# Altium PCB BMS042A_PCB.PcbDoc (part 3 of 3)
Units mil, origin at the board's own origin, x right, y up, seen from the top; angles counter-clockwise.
Board outline 4409.45 x 3307 mil, 6 copper layers (Top Layer, Layer 2 - PGND, Layer 3, Layer 4, Layer 5 - PGND, Bottom Layer), stack 60.8 mil thick; 273 components, 77 nets, 544 pads, 927 vias.
Unrouted connection lines stored in the file: 219.
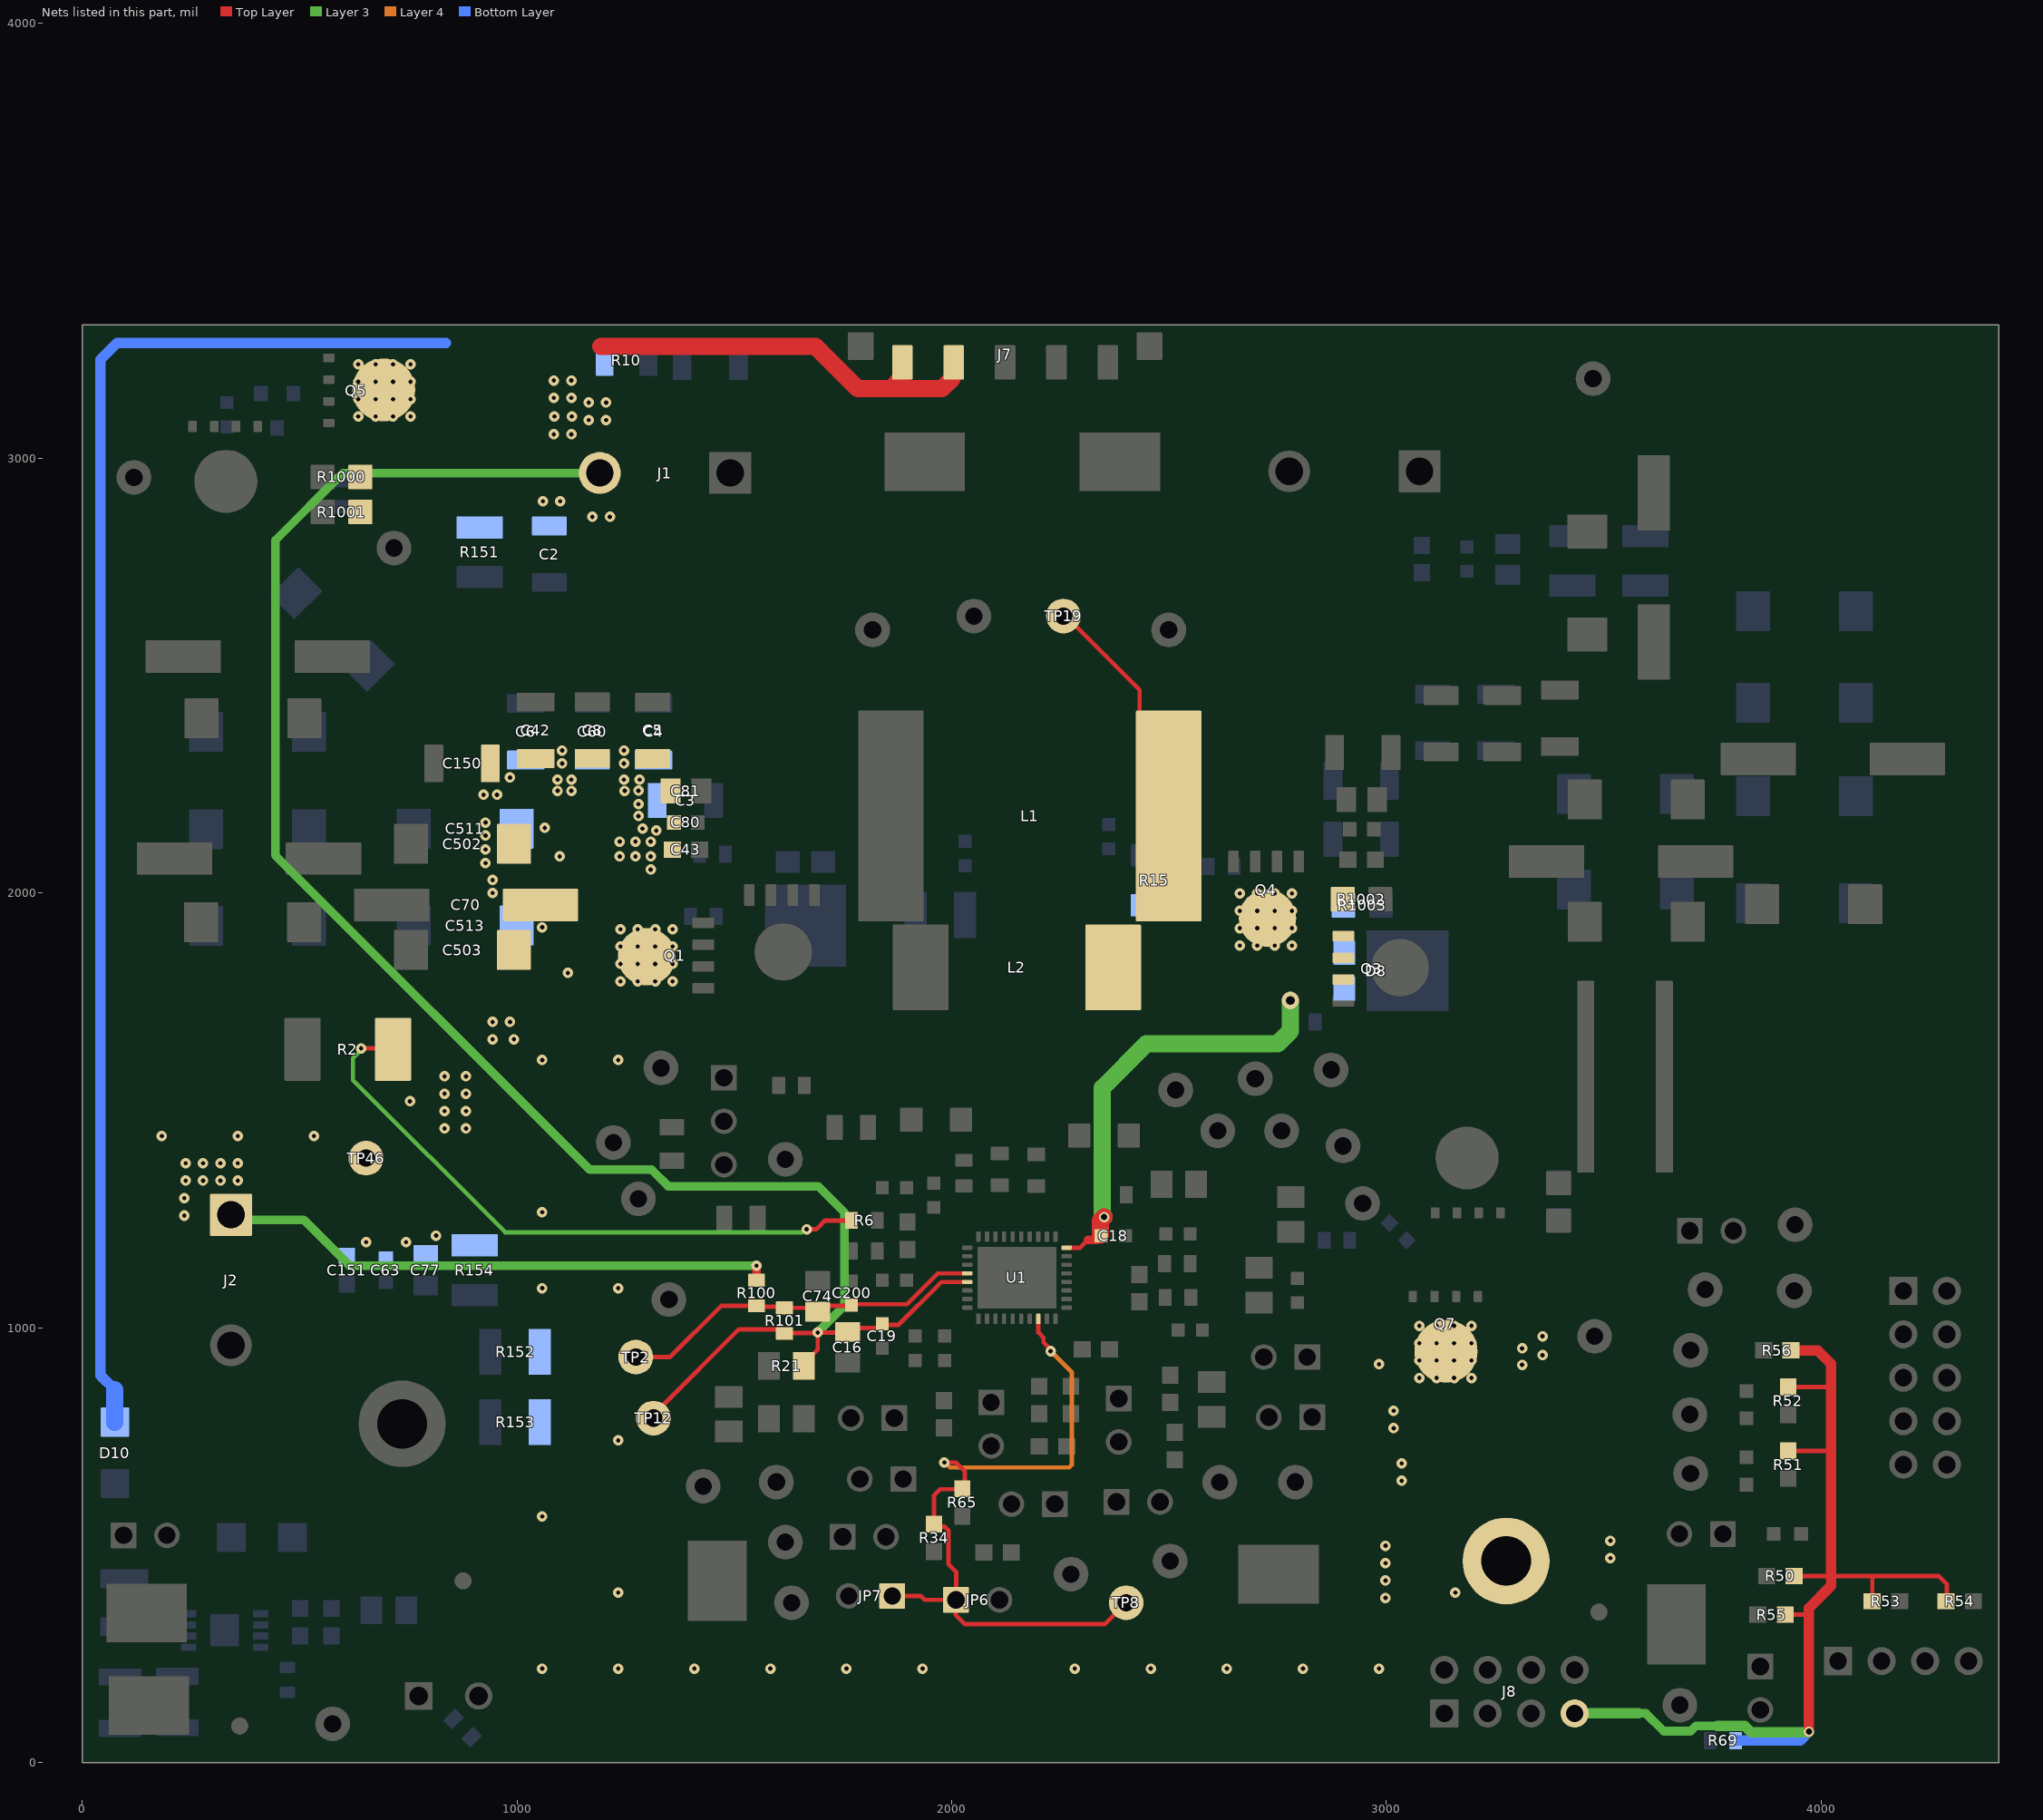
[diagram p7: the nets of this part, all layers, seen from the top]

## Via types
v1: diameter 24, hole 10, Top Layer to Bottom Layer, tented both sides, 653 vias
v2: diameter 24, hole 9.8, Top Layer to Bottom Layer, tented both sides, 132 vias
v3: diameter 24, hole 14, Top Layer to Bottom Layer, tented both sides, 105 vias
v4: diameter 40, hole 20, Top Layer to Bottom Layer, tented both sides, 21 vias
v5: diameter 19.68, hole 7.87, Top Layer to Bottom Layer, tented both sides, 16 vias

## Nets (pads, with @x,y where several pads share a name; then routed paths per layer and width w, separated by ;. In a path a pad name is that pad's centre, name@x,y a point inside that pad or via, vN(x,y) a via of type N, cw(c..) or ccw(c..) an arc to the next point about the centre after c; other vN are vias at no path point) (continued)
SW2: C18.2 D8.1 D8.2 L1.2 L2.2 Q3.1 Q3.2 Q3.3 Q4.5-6-7-8 R15.2 R1002.1 R1003.1 TP19.1 U1.18 | length 1557.2
  Top Layer w9.84: U1.18@2264.2,1184.14 2295.58,1184.14 2307.09,1195.65
  Top Layer w10: TP19.1@2257.14,2637 2262.19,2637 2432.23,2466.96 2432.23,2243.89 L1.2@2499.14,2176.98 ; 2307.09,1195.65 2313.22,1201.78 ; C18.2@2333.89,1201.78 C18.2@2343.89,1211.78 C18.2@2342.36,1213.31
  Top Layer w20: 2313.22,1201.78 C18.2@2333.89,1201.78
  Top Layer w40: C18.2@2342.36,1213.31 2342.36,1246.63 v3(2350.49,1254.76)
  Layer 3 w40: v3(2350.49,1254.76) 2346.55,1258.71 2346.55,1551.7 2448.01,1653.16 2750,1653.16 2779.2,1682.35 2779.2,1747.25 2779.02,1747.43 v4(2779.02,1752.79)
  other v2: 2662.9,1879.01 2702.9,1879.01 2742.9,1879.01 2782.9,1879.01 2662.9,1919.01 2702.9,1919.01 2742.9,1919.01 2782.9,1919.01 2662.9,1959.01 2702.9,1959.01 2742.9,1959.01 2782.9,1959.01 2662.9,1999.01 2702.9,1999.01 2742.9,1999.01 2782.9,1999.01
SYS: C74.1 C200.1 R100.1 R101.2 TP2.1 U1.32 | length 848.7
  Top Layer w9.84: 1967.91,1125.09 U1.32@2035.85,1125.09
  Top Layer w10: TP2.1@1273.45,932.59 1351.94,932.59 1469.74,1050.39 R100.1@1551.11,1050.39 1553.42,1048.08 R101.2@1612.97,1048.08 ; R101.2@1615.29,1045.77 1682.9,1045.77 C74.1@1691.61,1037.06 ; C74.1@1690.6,1050.28 1768.18,1050.28 C200.1@1769.58,1051.68 1772.12,1054.22 1897.12,1054.22 1967.91,1125.01
  Top Layer w20: R101.2@1612.97,1048.08 R101.2@1615.29,1045.77
TS: JP6.1 JP7.1 R34.1 R65.2 TP8.1 U1.8 | length 1718.5
  Top Layer w9.84: 2199.23,989.1 U1.8@2199.23,1020.76
  Top Layer w10: JP7.1@1863.1,383.15 1928.48,383.15 1937.56,374.06 JP6.1@2009.85,374.06 ; v1(1983.09,690) 2010.14,690 2030.1,670.04 2030.1,635.59 2024.4,629.89 R65.2@2024.57,629.73 2023.38,628.54 1973.23,628.54 1959.43,614.74 R34.1@1959.43,548.32 1959.43,547.33 1964.28,542.49 1984.17,542.49 1992.97,533.69 1992.97,455.32 2010.62,437.68 2010.62,374.83 JP6.1@2009.85,374.06 ; 2199.31,989.13 2211.07,977.37 2211.07,966.31 2227.42,949.96 v1(2227.42,946.17) ; TP8.1@2401.38,367.5 2351.96,318.08 2030.53,318.08 2009.27,339.34 2009.27,373.48 JP6.1@2009.85,374.06
  Layer 4 w10: v1(1983.09,690) 1984.75,690 1995.95,678.8 2270.51,678.8 2276.36,684.66 2276.36,897.23 v1(2227.42,946.17)
VAC: C2.2 C16.1 C19.1 D10.2 J1.2 J7.4 J7.5 Q5.5-6-7-8 R10.2 R21.2 R101.1 R151.2 R1000.1 R1001.1 TP12.1 U1.33 | length 8694.4
  Top Layer w9.84: 1970.39,1099.43 1970.39,1099.54 1976.25,1105.4 U1.33@2035.85,1105.4
  Top Layer w10: TP12.1@1314.24,760.32 TP12.1@1314.24,808.29 ; TP12.1@1331,816.81 1510.48,996.29 1605.71,996.29 R101.1@1615.29,986.72 1616.48,987.91 1690.42,987.91 v1(1691.61,989.1) ; R21.2@1659.96,912.07 1659.96,918.57 1691.61,950.22 v1(1691.61,989.1) ; C19.1@1840.37,1006.65 1877.61,1006.65 1970.39,1099.43 ; C19.1@1840.37,1009.03 1830.81,999.46 1769.89,999.46 C16.1@1760.89,990.46 1759.53,989.1 v1(1691.61,989.1)
  Top Layer w40: 1192.48,3257 1686.95,3257 1783.96,3160 1859.64,3160 ; J7.5@1886.69,3220.53 1883.07,3216.91 1883.07,3183.43 1859.64,3160 ; J7.4@2004.8,3220.53 2001.18,3216.91 2001.18,3183.43 1977.75,3160 1859.64,3160
  Layer 3 w20: J1.2@1190.42,2966.06 599.06,2966.06 444.49,2811.49 444.49,2086.51 1167.49,1363.51 1310.1,1363.51 1347.99,1325.63 1692.8,1325.63 1753.69,1264.73 1753.69,1051.18 v1(1691.61,989.1)
  Bottom Layer w24: 75,857.5 42,890.5 42,3226.94 80.06,3265 836.73,3265
  Bottom Layer w40: D10.2@75,782.97 75,857.5
  other v1: 1173.64,2865.32 1213.64,2865.32 1059.62,2901.32 1099.62,2901.32 1085,3055 1125,3055 1165,3088 1205,3088 1086.2,3095.93 1126.2,3095.93 1165,3128 1205,3128 1085,3139 1125,3139 1085,3179 1125,3179
  other v2: 635,3096 675,3096 715,3096 755,3096 635,3136 675,3136 715,3136 755,3136 635,3176 675,3176 715,3176 755,3176 635,3216 675,3216 715,3216 755,3216
VIN3V3: J8.7 R50.2 R51.2 R52.2 R53.2 R54.2 R55.2 R56.2 R69.2 | length 2429.6
  Top Layer w10: R55.2@3917.5,340 3972,340 ; R52.2@3924,863.5 4018.24,863.5 4022.98,858.76 ; R51.2@3924.56,716.6 4020.57,716.6 4022.98,719 ; R50.2@3937.54,429 4022.98,429 4119,429 ; R53.2@4117.5,371 4117.5,427.5 4119,429 ; R54.2@4290.5,371 4289,372.5 4289,410.16 4270.16,429 4119,429
  Top Layer w24: R56.2@3930.5,948 3992,948 4022.98,917.02 4022.98,858.76 4022.98,719 4022.98,429 4022.98,406.28 3972,355.3 3972,340 v3(3972,71)
  Layer 3 w20: 3579.97,113 3597,113 3637.84,72.16 3699.79,72.16 3711.92,84.29 3760.83,84.29
  Layer 3 w24: J8.7@3433,113 3579.97,113 ; 3760.83,84.29 3824.06,84.29 3838.72,69.63 3970.63,69.63 v3(3972,71)
  Bottom Layer w24: R69.2@3803.53,50.37 3804.16,51 3952,51 v3(3972,71)
VSYS: C3.1 C4.1 C5.2 C6.1 C8.2 C42.2 C43.1 C60.1 C63.1 C70.2 C77.1 C80.1 C81.1 C150.2 C151.1 C502.2 C503.2 C511.2 C513.2 J2.1 pad.Pad1 Q1.5-6-7-8 Q7.5-6-7-8 R2.2 R6.2 R100.2 R152.2 R153.2 R154.2 TP46.1 | length 2748.3
  Top Layer w10: v1(641.66,1642.82) 712.64,1642.82 R2.2@714.95,1640.5 ; v1(1666.43,1226.63) 1688.77,1226.63 1708.69,1246.56 R6.2@1769.13,1246.56
  Top Layer w20: R100.2@1551.11,1109.45 v1(1551.11,1142.91)
  Layer 3 w10: v1(641.66,1642.82) 641.66,1639.03 623,1620.37 623,1569.5 972.87,1219.63 1655.64,1219.63 1662.64,1226.63 v1(1666.43,1226.63)
  Layer 3 w20: J2.1@342.13,1259.78 353.66,1248.25 509.25,1248.25 614.59,1142.91 v1(1551.11,1142.91)
  other v1: 1058,216 1233,216 1408,216 1583,216 1758,216 1933,216 2283,216 2458,216 2633,216 2808,216 2983,216 2998.01,378.52 1233,391 3158.45,390.71 2998.01,418.52 2998.01,458.52 3515.1,470.12 2998.01,498.52 3515.1,510.12 1058,566 3035.1,647.91 3035.1,687.91 1233,741 3016.59,769.13 3016.59,809.13 3312,914.85 2983,916 3359,936.87 3312,952.64 3359,980.4 1058,1091 1233,1091 653,1197 745,1197 814,1212 235,1258 1058,1266 235,1298 238,1338.61 278,1338.61 318,1338.61 358,1338.61 238,1378.61 278,1378.61 318,1378.61 358,1378.61 183,1441 358,1441 533,1441 833.55,1458.45 882.81,1458.45 833.55,1498.45 882.81,1498.45 754,1521 833.55,1538.45 882.81,1538.45 833.55,1578.45 882.81,1578.45 1058,1616 1233,1616 943.9,1663.4 993.16,1663.4 943.9,1703.4 983.95,1703.4 1117,1816 1058.04,1921.2 943.95,1999.99 943.9,2030 1307.79,2054 927.58,2069.01 1098.49,2084 1236.46,2084 1272.48,2084 1307.79,2084 927.58,2100 1236.46,2118.27 1272.48,2118.27 1307.79,2118.27 927.58,2132 1320.71,2143.66 1288.74,2148.22 1063.95,2149.84 927.58,2162.04 1279.4,2176.98 1279.4,2204.55 923,2225.92 954,2225.92 1093.62,2235.16 1125,2235 1247.74,2235 1279.39,2235.23 1093.62,2260.73 1125,2260.73 1246,2260.73 1282.16,2260.73 983.95,2265.72 1103.95,2297.91 1246,2297.91 1104,2328 1246,2328
  other v2: 3075.65,884.56 3115.65,884.56 3155.65,884.56 3195.65,884.56 3075.65,924.56 3115.65,924.56 3155.65,924.56 3195.65,924.56 3075.65,964.56 3115.65,964.56 3155.65,964.56 3195.65,964.56 3075.65,1004.56 3115.65,1004.56 3155.65,1004.56 3195.65,1004.56 1237.97,1796.89 1277.97,1796.89 1317.97,1796.89 1357.97,1796.89 1237.97,1836.89 1277.97,1836.89 1317.97,1836.89 1357.97,1836.89 1237.97,1876.89 1277.97,1876.89 1317.97,1876.89 1357.97,1876.89 1237.97,1916.89 1277.97,1916.89 1317.97,1916.89 1357.97,1916.89
pads on no net: D1.2 FID1.1 FID2.1 FID3.1 FID4.1 FID5.1 FID6.1 H1.0 H2.0 H3.0 H4.0 J4.1 J4.2 J4.3 J4.4 J4.5 J4.7 J4.8 J5.4 LBL1.0 SH-JP1.0 SH-JP2.0 SH-JP3.0 SH-JP4.0 SH-JP5.0 SH-JP6.0 SH-JP7.0 SH-JP8.0 SH-JP9.0 SH-JP10.0 SH-JP11.0 U2.3 U2.6 U2.7

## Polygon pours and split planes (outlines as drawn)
PGND on Top Layer "TOP_LAYER_PGND_P669" (solid, remove dead copper, pour order 669): 1,3310 1,-1 4409.45,-1 4409.45,3304.45 4410,3305 2,3305 0,3307
BAT on Top Layer "TOP_LAYER_BAT_P668" (solid, remove dead copper, pour order 668): 3428,1838.67 3428,1307 4434,1307 4434,3309 4436,3311 2939.16,3311 2939.16,2781 3971,2781 3971,1838.67
VSYS on Top Layer "Top Layer-NetC3_1" (solid, remove dead copper, pour order 621): 0,1145 1001,1145 1001,-1 3539.82,-1 3539.82,1052.11 2944.31,1052.11 2944.31,318.08 1326.85,318.08 1326.85,1443.5 1376.14,1443.5 1376.14,2350.2 897.88,2350.2 897.88,1792.06 623,1791.94 623,1479.85 0,1480.09
SW1 on Top Layer "TOP_LAYER_SW1_P636" (solid, remove dead copper, pour order 636): 1387.59,1942.21 1759.9,1942.21 1759.9,2443.4 1999.6,2443.4 2035.85,2443.4 2035.85,1640.5 1387.59,1640.5
AC_OUT on Top Layer "Top Layer-NetC7_2" (solid, remove dead copper, pour order 626): -26,1468 679.82,1468 679.82,1794 429,1794 429,2615.1 584,2615.1 584,3032 -25,3032 -25,2980 -26,2979
NetC9_1 on Top Layer "TOP_LAYER_NETC9_1_P627" (solid, remove dead copper, pour order 627): 585,3312 583,3310 583,3055 -14,3055 -14,3314 584,3314
P_OUT on Top Layer "TOP_LAYER_P_OUT_P628" (solid, remove dead copper, pour order 628): 2955.65,1305.62 3539.82,1305.62 3539.82,2372.28 2955.65,2372.28
BAT_SRC on Top Layer "TOP_LAYER_BAT_SRC_P607" (solid, remove dead copper, pour order 607): 2955.65,1280.39 3539.82,1280.39 3539.82,1054.04 2955.65,1054.04
VAC on Top Layer "TOP_LAYER_VAC_P616" (solid, remove dead copper, pour order 616): 1328.47,3314 1328.47,2795.71 610,2795.71 610,2918.6 610,3314
SW2 on Top Layer "TOP_LAYER_SW2_P662" (solid, remove dead copper, pour order 662): 2254.33,2443.4 2254.33,1720.27 2932.21,1720.27 2933.1,1721.16 2929,1725.26 2929,2019.87 2591.58,2019.87 2591.58,2443.4
PGND on Layer 3 "LAYER_3_-_PGND_PGND_P550" (solid, remove dead copper, pour order 673): 4409.45,-5 5,-5 0,0 0,3343.16 4409.45,3343.16
VAC on Layer 3 "Layer 3-VAC" (solid, remove dead copper, pour order 603): 460,2881.6 1282.14,2881.6 1280,2883.74 1280,3311 0,3311 0,3119.74 460,3119.74
AC_OUT on Layer 3 "LAYER_3_AC_OUT_P657" (solid, remove dead copper, pour order 657): 0,3134 444.49,3134 444.49,2343.58 0,2343.58
P_OUT on Layer 3 "LAYER_3_P_OUT_P658" (solid, remove dead copper, pour order 658): 2674.99,2096.96 2674.99,1598.6 3359.4,1598.6 3465,1598.6 3465,2096.96
P_OUT on Layer 3 "LAYER_3_P_OUT_P659" (solid, remove dead copper, pour order 659): 3011.93,1152.03 3405.1,1152.03 3405.1,1662.47 3011.93,1662.47
VSYS on Layer 3 "LAYER_3_VSYS_P660" (solid, remove dead copper, pour order 660): 1081.81,2139.21 1085,2136.02 1085,1676 1495.82,1676 1486.12,1685.69 1486.12,2139.21
VSYS on Layer 3 "LAYER_3_VSYS_P672" (solid, remove dead copper, pour order 672): 2925.9,839.53 3481.13,839.53 3481.13,1088 2925.9,1088
PGND on Layer 4 "LAYER_4_PGND_P671" (solid, remove dead copper, pour order 671): 1,3310 1,-1 4409.45,-1 4409.45,3304.45 4410,3305 2,3305 0,3307
BAT on Layer 4 "LAYER_4_BAT_P670" (solid, remove dead copper, pour order 670): 3428,1838.67 3428,1307 4434,1307 4434,3309 4436,3311 2939.16,3311 2939.16,2781 3971,2781 3971,1838.67
VSYS on Layer 4 "LAYER_4_VSYS_P640" (solid, remove dead copper, pour order 640): 0,1145 1001,1145 1001,-1 3539.82,-1 3539.82,1052.11 2944.31,1052.11 2944.31,318.08 1326.85,318.08 1326.85,1443.5 1376.14,1443.5 1376.14,2350.2 897.88,2350.2 897.88,1792.06 623,1791.94 623,1479.85 0,1480.09
AC_OUT on Layer 4 "LAYER_4_AC_OUT_P641" (solid, remove dead copper, pour order 641): -26,1468 679.82,1468 679.82,1794 429,1794 429,2615.1 584,2615.1 584,3032 -25,3032 -25,2980 -26,2979
P_OUT on Layer 4 "LAYER_4_P_OUT_P643" (solid, remove dead copper, pour order 643): 2955.65,1305.62 3539.82,1305.62 3539.82,2372.28 2955.65,2372.28
BAT_SRC on Layer 4 "LAYER_4_BAT_SRC_P637" (solid, remove dead copper, pour order 637): 2955.65,1280.39 3539.82,1280.39 3539.82,1054.04 2955.65,1054.04
VAC on Layer 4 "LAYER_4_VAC_P639" (solid, remove dead copper, pour order 639): 1328.47,3314 1328.47,2795.71 610,2795.71 610,2918.6 610,3314
NetC9_1 on Layer 4 "LAYER_4_NETC9_1_P642" (solid, remove dead copper, pour order 642): 585,3312 583,3310 583,3055 -14,3055 -14,3314 584,3314
SW1 on Layer 4 "LAYER_4_SW1_P644" (solid, remove dead copper, pour order 644): 1387.98,2019.87 1746.9,2019.87 1958.45,2019.87 1958.45,1725.95 1389.38,1725.95 1387.98,1727.36
SW2 on Layer 4 "LAYER_4_SW2_P646" (solid, remove dead copper, pour order 646): 2339.6,2019.87 2339.6,1720.27 2932.21,1720.27 2933.1,1721.16 2929,1725.26 2929,2019.87 2591.58,2019.87
PGND on Bottom Layer "BOTTOM_LAYER_PGND_P656" (solid, remove dead copper, pour order 656): 1,3310 1,-1 4409.45,-1 4409.45,3304.45 4410,3305 2,3305 0,3307
BAT on Bottom Layer "BOTTOM_LAYER_BAT_P655" (solid, remove dead copper, pour order 655): 3428,1838.67 3428,1307 4434,1307 4434,3309 4436,3311 2939.16,3311 2939.16,2781 3971,2781 3971,1838.67
VSYS on Bottom Layer "BOTTOM_LAYER_VSYS_P649" (solid, remove dead copper, pour order 649): 0,1145 1001,1145 1001,-1 3539.82,-1 3539.82,1052.11 2944.31,1052.11 2944.31,318.08 1326.85,318.08 1326.85,1443.5 1376.14,1443.5 1376.14,2350.2 897.88,2350.2 897.88,1792.06 623,1791.94 623,1479.85 0,1480.09
VAC on Bottom Layer "BOTTOM_LAYER_VAC_P648" (solid, remove dead copper, pour order 648): 1328.47,3314 1328.47,2795.71 610,2795.71 610,2918.6 610,3314
AC_OUT on Bottom Layer "BOTTOM_LAYER_AC_OUT_P650" (solid, remove dead copper, pour order 650): -26,1468 679.82,1468 679.82,1794 429,1794 429,2615.1 584,2615.1 584,3032 -25,3032 -25,2980 -26,2979
NetC9_1 on Bottom Layer "BOTTOM_LAYER_NETC9_1_P651" (solid, remove dead copper, pour order 651): 585,3312 583,3310 583,3055 -14,3055 -14,3314 584,3314
P_OUT on Bottom Layer "BOTTOM_LAYER_P_OUT_P652" (solid, remove dead copper, pour order 652): 2955.65,1305.62 3539.82,1305.62 3539.82,2372.28 2955.65,2372.28
BAT_SRC on Bottom Layer "BOTTOM_LAYER_BAT_SRC_P647" (solid, remove dead copper, pour order 647): 2955.65,1280.39 3539.82,1280.39 3539.82,1054.04 2955.65,1054.04
SW1 on Bottom Layer "BOTTOM_LAYER_SW1_P653" (solid, remove dead copper, pour order 653): 1387.98,2019.87 1746.9,2019.87 1958.45,2019.87 1958.45,1725.95 1389.38,1725.95 1387.98,1727.36
SW2 on Bottom Layer "BOTTOM_LAYER_SW2_P654" (solid, remove dead copper, pour order 654): 2339.6,2019.87 2339.6,1720.27 2932.21,1720.27 2933.1,1721.16 2929,1725.26 2929,2019.87 2591.58,2019.87
PGND on Layer 2 - PGND "LAYER_2_-_PGND_PGND_P532" (solid, remove dead copper, pour order 532): 4409.45,-5 5,-5 0,0 0,3345 4409.45,3345
PGND on Layer 5 - PGND "LAYER_5_-_PGND_PGND_P533" (solid, remove dead copper, pour order 533): 4409.45,-5 5,-5 0,0 0,3545 4409.45,3545

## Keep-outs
Keep-Out Layer:
  text ".Layer_Name" at 577,-858.49 h60

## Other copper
Top Layer:
  pour cut-out: 2688.25,1309.19 2688.25,1277.84 2726.91,1277.84 2726.91,1309.19
  pour cut-out: 1425.89,1450.68 1425.89,1397.38 1530.79,1397.38 1530.79,1450.68
  pour cut-out: 2467.39,1127.84 2506.56,1127.84 2506.77,1128.04 2506.77,1178.74 2530.27,1178.74 2531.01,1177.99 2531.01,1129.62 2577.19,1129.62 2577.19,1093.93 2537.36,1093.93 2537.36,1046.35 2504,1046.35 2504,1090.99 2467.39,1090.99
  pour cut-out: 1319.97,1443.5 1393.67,1443.5 1394.22,1444.05 1394.22,1398.42 1395.27,1397.38 1394.89,1397 1319.97,1397
  pour cut-out: 1489.27,1299.47 1489.27,1213.4 1539.29,1213.4 1539.29,1298.48 1538.3,1299.47
  pour cut-out: 2311.62,1393.16 2397.9,1393.16 2397.9,1493.79 2311.62,1493.79
  pour cut-out: 1926,1416.62 1928.4,1416.62 2008.11,1416.62 2008.11,1510 2005.2,1507.09 1926,1507.09
  pour cut-out: 1929.02,1014.94 1929.02,949.12 1970.39,949.12 1970.39,1014.94
  pour cut-out: 1604.81,963.14 1604.81,864.77 1635.27,864.77 1635.27,963.14
  pour cut-out: 2224,858 2223.78,857.78 2223.78,750.79 2259.46,750.79 2259.46,857.99 2224.66,857.99 2224.44,857.77
  pour cut-out: 2557.71,815.35 2641.73,815.35 2641.73,857.77 2641.29,858.21 2557.71,858.21
  pour cut-out: 2666.72,1113.36 2667.13,1112.95 2667.13,1082 2748.89,1082 2748.89,1114.24 2667.13,1114.24
  pour cut-out: 2735.95,1278.68 2735.95,1242.58 2822.75,1242.58 2824.04,1241.28 2824.26,1241.5 2824.26,1278.68
  pour cut-out: 1525.9,1063.08 1581.81,1063.08 1581.81,1095.54 1582.87,1096.6 1525.9,1096.6
  pour cut-out: 525.99,1607.72 698.26,1607.72 698.26,1676.72 525.99,1676.72
  pour cut-out: 2846,3305 2846,2761.37 3005.11,2761.37 3005.11,3305
  pour cut-out: 1266.02,2761.82 1419.05,2761.82 1419.05,3310 1266.02,3310
  pour cut-out: 2584.26,1143.82 2584.26,1057.06 2621.69,1057.06 2621.69,1143.82
  pour cut-out: 3456.32,1553.5 3642,1553.5 3642,1634.58 3456.32,1634.58
  pour cut-out: 1634.67,1256 1634.67,1158.56 1704.41,1158.56 1704.56,1158.72 1704.56,1256
  pour cut-out: 2043,2454 2043,1602.34 2285.6,1602.34 2285.6,2454
  pour cut-out: 1532.05,1159.24 1532.05,1127.89 1570.7,1127.89 1570.7,1159.24
  pour cut-out: 1672.07,1003.82 1672.07,972.47 1710.73,972.47 1710.73,1003.82
  pour cut-out: 1782.42,1278.77 1782.42,1156.91 1783.21,1156.13 1783.62,1156.54 1813.83,1156.54 1813.83,1276.81 1815.79,1278.77
  pour cut-out: 533.1,1058.38 533.1,1208.06 -6.9,1208.06 -6.9,1058.38
  pour cut-out: 1746.9,1496.96 1772.9,1496.96 1797.33,1496.96 1797.33,1428.96 1746.9,1428.96 1746.9,1430.96
Layer 2 - PGND:
  pour cut-out: 2688.25,1309.21 2688.25,1277.86 2726.91,1277.86 2726.91,1309.21
  pour cut-out: 525.99,1607.72 698.26,1607.72 698.26,1676.72 525.99,1676.72
  pour cut-out: 1532.05,1159.24 1532.05,1127.89 1570.7,1127.89 1570.7,1159.24
  pour cut-out: 2584.26,1143.82 2584.26,1057.06 2621.69,1057.06 2621.69,1143.82
  pour cut-out: 3482.18,1557.54 3616.35,1557.54 3616.35,1628.54 3482.18,1628.54
  pour cut-out: 1672.07,1003.84 1672.07,972.49 1710.73,972.49 1710.73,1003.84
  pour cut-out: 1634.67,1256 1634.67,1158.56 1704.41,1158.56 1704.56,1158.72 1704.56,1256
Layer 3:
  pour cut-out: 2733.35,1333.97 2733.35,1277.61 2733.26,1277.52 2732.92,1277.86 2682.69,1277.86 2682.69,1333.97
  pour cut-out: 2688.53,1309.21 2688.53,1277.86 2727.18,1277.86 2727.18,1309.21
  pour cut-out: 2817.87,1646.84 2817.87,1534.74 2927.38,1534.74 2927.38,1646.84
  pour cut-out: 525.99,1607.72 698.26,1607.72 698.26,1676.72 525.99,1676.72
  pour cut-out: 1668.99,1000.48 1729.05,1060.54 1729.05,1247.17 1678.1,1298.12 1331.21,1298.12 1290.41,1338.93 1290.41,1342.4 1146.12,1342.4 406,2082.52 406,2842 561.88,2997.88 1172,2997.88 1172,2934 623.33,2934 484,2794.67 484,2090.09 1177.09,1397 1331.21,1397 1368,1360.21 1368,1356 1369,1357 1369,1358 1695.88,1358 1775.11,1278.77 1775.11,1036.59 1707.65,969.13
  pour cut-out: 358,1229 484.59,1229 600.36,1113.23 1574.72,1113.23 1574.72,1169.02 1575.32,1169.62 1575.32,1169.68 626.72,1169.68 506.4,1290 358,1290
  pour cut-out: 1532.05,1159.24 1532.05,1127.89 1570.7,1127.89 1570.7,1159.24
  pour cut-out: 2584.26,1143.82 2584.26,1057.06 2621.69,1057.06 2621.69,1143.82
  pour cut-out: 3482.18,1557.54 3616.35,1557.54 3616.35,1628.54 3482.18,1628.54
  pour cut-out: 2572.08,1147.83 2572.08,1138.92 2572.08,1055.31 3359.31,1055.31 3580.35,1276.35 3580.35,1572.84 3515.1,1572.84 3515.1,1339.9 3323.03,1147.83
  pour cut-out: 552.97,1665.91 552.97,1578.03 954.73,1176.27 1650.88,1176.27 1650.88,1246.42 1651.72,1247.26 970.74,1247.26 672.21,1545.79 672.21,1665.91
  pour cut-out: 2693.67,1333.97 3109.48,1742.76 3109.48,2894.15 3077.56,2926.08 3122.13,2970.65 3148.23,2944.54 3148.23,1726.87 2723.19,1301.82
  pour cut-out: 1672.35,1003.84 1672.35,972.49 1711.01,972.49 1711.01,1003.84
  pour cut-out: 1634.67,1256 1634.67,1158.56 1704.41,1158.56 1704.56,1158.72 1704.56,1256
Layer 4:
  pour cut-out: 2688.33,1309.52 2688.33,1278.17 2726.99,1278.17 2726.99,1309.52
  pour cut-out: 525.99,1607.72 698.26,1607.72 698.26,1676.72 525.99,1676.72
  pour cut-out: 1532.05,1159.24 1532.05,1127.89 1570.7,1127.89 1570.7,1159.24
  pour cut-out: 2584.26,1143.82 2584.26,1057.06 2621.69,1057.06 2621.69,1143.82
  pour cut-out: 3482.18,1557.54 3616.35,1557.54 3616.35,1628.54 3482.18,1628.54
  pour cut-out: 1672.16,1004.15 1672.16,972.8 1710.82,972.8 1710.82,1004.15
  pour cut-out: 1634.67,1256 1634.67,1158.56 1704.41,1158.56 1704.56,1158.72 1704.56,1256
Layer 5 - PGND:
  pour cut-out: 2688.53,1309.21 2688.53,1277.86 2727.18,1277.86 2727.18,1309.21
  pour cut-out: 525.99,1607.72 698.26,1607.72 698.26,1676.72 525.99,1676.72
  pour cut-out: 1532.05,1159.24 1532.05,1127.89 1570.7,1127.89 1570.7,1159.24
  pour cut-out: 2584.26,1143.82 2584.26,1057.06 2621.69,1057.06 2621.69,1143.82
  pour cut-out: 3482.18,1557.54 3616.35,1557.54 3616.35,1628.54 3482.18,1628.54
  pour cut-out: 1672.35,1003.84 1672.35,972.49 1711.01,972.49 1711.01,1003.84
  pour cut-out: 1634.67,1256 1634.67,1158.56 1704.41,1158.56 1704.56,1158.72 1704.56,1256
Bottom Layer:
  pour cut-out: 1399.43,3270.14 1399.43,3174.96 1489.86,3174.96 1489.86,3270.24 1489.33,3270.78 1399.41,3270.78
  pour cut-out: 1222.34,3263.9 1222.34,3187.9 1283.34,3187.9 1283.34,3263.82 1282.25,3264.9 1281.25,3263.9 1223.34,3263.9
  pour cut-out: 2688.53,1309.21 2688.53,1277.86 2727.18,1277.86 2727.18,1309.21
  pour cut-out: 1,163 279.53,163 280,163.47 281.11,162.36 281.11,104.04 1.21,104.04 0.44,103.27 0,103.71 0,161.64
  pour cut-out: 361,599 361,435 472.11,435 472.11,596.85 469.97,599
  pour cut-out: 18.03,407 169.78,407 169.78,327.48 18.03,327.48
  pour cut-out: 116.03,563.03 116.03,481.81 181.83,481.81 181.83,563.03
  pour cut-out: 15,747.78 142.02,747.78 142.02,677.22 15,677.22
  pour cut-out: 525.99,1607.72 698.26,1607.72 698.26,1676.72 525.99,1676.72
  pour cut-out: 1532.05,1159.24 1532.05,1127.89 1570.7,1127.89 1570.7,1159.24
  pour cut-out: 2584.26,1143.82 2584.26,1057.06 2621.69,1057.06 2621.69,1143.82
  pour cut-out: 3482.18,1557.54 3616.35,1557.54 3616.35,1628.54 3482.18,1628.54
  pour cut-out: 1672.35,1003.84 1672.35,972.49 1711.01,972.49 1711.01,1003.84
  pour cut-out: 1634.67,1256 1634.67,1158.56 1704.41,1158.56 1704.56,1158.72 1704.56,1256

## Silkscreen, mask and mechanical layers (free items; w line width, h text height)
Top Overlay:
  text "VOUT" at 3299,3271.51 h82.68 r270
  text "PGND" at 2515,3237 h82.68 r270
  text "VIN" at 915.78,3176.76 h82.68 r270
  text "PGND" at 1721.8,3118 h82.68 r270
  text "'.PRJ_Number'.PCB_Rev" at 3844,2964 h108.27
  text "SEE" at 2078,2926 h78.74
  text "USER'S GUIDE" at 1834.56,2805.71 h78.74
  text "ACDRV" at 775,2727 h35
  text "FOR I/O RANGE" at 1731.86,2706.57 h78.74 r0.28
  text "-" at 2720.54,2657.49 h82.68
  text "-" at 1505.93,2647.13 h82.68
  text "+" at 1085,2643.22 h82.68
  text "SW1" at 1882.1,2642 h35
  text "SW2" at 2345.56,2642 h35
  text "+" at 3103.82,2630.22 h82.68
  text "LODRV2" at 2590,2568 h35
  text "LODRV1" at 1555.07,2566.32 h35
  text "BTST2" at 2460.08,1727.53 h35
  text "--->" at 2480.66,1684.25 h20 r270
  text "MODE" at 2667.41,1636.57 h35
  text "SRP" at 2545.26,1612.1 h35
  text "HIDRV1" at 1068.95,1611.07 h35
  text "--->" at 2592.08,1602.34 h20 r270
  text "+" at 1839.29,1550.72 h30 r270
  text "+" at 2272.55,1537.86 h30 r270
  text "-->" at 2990.03,1535.16 h20 r225
  text "HIDRV2" at 3015.7,1519.86 h35
  text "------>" at 1862.82,1394.28 h20
  text "DRV_SUP" at 921,1386.83 h35
  text "SRN" at 2707.9,1353.9 h35
  text "ACN" at 1653.25,1301.53 h35
  text "SDA" at 4015.72,1280 h35 r270
  text "ACP" at 1113,1237 h35
  text "+" at 920.22,1232.81 h82.68 r270
  text "--->" at 3084.86,1192.66 h20 r135
  text "VSYS" at 577,1182 h82.68
  text "BATDRV" at 3065.7,1135.78 h35
  text "SCL" at 4012.66,1131.1 h35 r270
  text "BTST1" at 1138,1092.65 h35
  text "CE" at 3592.82,1059.5 h35
  text "-" at 828,979.67 h82.68
  text "-->" at 2243.6,956.05 h20 r270
  text "PG" at 3568.9,950.81 h35
  text "SYS" at 1108,949.55 h35
  text "--->" at 2137.64,949.96 h20 r315
  text "EXT_I2C" at 4018.58,947.64 h35 r270
  text "PGND" at 579.44,890.78 h82.68
  text "STAT2" at 3601,887.49 h30 r270
  text "BATSRC" at 3333.71,874.42 h35
  text "VAC" at 1150,800 h35
  text "STAT1" at 3591.31,717.12 h30 r270
  text "REFER TO" at 42.57,692 h78.74
  text "--------->" at 1319.24,691.59 h20
  text "ACOV" at 1178.36,681.95 h35
  text "->" at 1503.2,679.42 h20 r315
  text "--->" at 1287.93,619.74 h20
  text "ACUV" at 1137,615.44 h35
  text "USER'S GUIDE" at 250,574.11 h78.74
  text "->" at 1536.38,554.9 h20 r315
  text "--------->" at 1340.76,553.32 h20
  text "FSW_SYNC" at 1049,544.52 h35
  text "FBG" at 2575.61,539.35 h35
  text "FB" at 2790,535.74 h35
  text "FOR I/O" at 327.9,451.66 h78.74 r0.28
  text "EXT_I2C" at 4066,430.83 h35
  text "RANGE" at 418,328.13 h78.74 r0.28
  text "-->" at 2261.63,318.08 h20 r90
  text "------>" at 2648.47,316.03 h20 r135
  text "PGND" at 1363.67,275 h50 r90
  text "TS" at 2429.47,272 h35
  text "ICHG" at 2186,271 h35
  text "REGN" at 1566,268 h35
  text "ILIM_HIZ" at 2576.42,258.83 h35
  text "PGND" at 479,233 h50
  text "/INT" at 3572.44,183 h35 r270
  text "EXT_DRV" at 1077.67,169 h50 r90
  text "11V MAX" at 1148,169 h50 r90
  text "3V3" at 490,159 h30
Bottom Overlay:
  text "CAUTION." at 2609.71,2718.02 h82.68
  text "READ USER GUIDE" at 2776.54,2412 h82.68
  text "BEFORE USE" at 2557.21,2291 h82.68
  text "+" at 210.66,1288 h100 r90
  text "EXT_I2C" at 4092.67,1165 h80 r90
  text "-" at 209.6,1070.32 h100 r90
  text "DIODE+" at 283,784 h25
  text "+" at 516.75,603.54 h30 r90
  text "EXT_I2C" at 4344,346.33 h80
  text "For Demo Purposes Only." at 2613,231 h45
  text "Not for Diagnostic or Therapeutic Use." at 3027,81 h45
Top Paste:
  text ".Layer_Name" at 10161,186 h60
Bottom Paste:
  text ".Layer_Name" at 10182,52 h60
Drill Guide:
  text ".Layer_Name" at 577,-858.49 h60
M1 Board Outline:
  the board outline again, w10
  text ".Layer_Name" at 10177,-355 h60
M2 Board Dimensions:
  rectangle: 0,-275 125,-150
  rectangle: 125,-400 500,-275
  lines w7: 0,-275 1000,-275 ; 125,-400 125,-150 ; 250,-400 250,-150 ; 500,-400 500,-150 ; 750,-400 750,-150 ; 0,-400 1000,-400 1000,-150 0,-150 0,-400
  text ".Layer_Name" at 577,-858.49 h60
M3 3D STEP Top:
  text ".Layer_Name" at 10199,-205 h60
M4 3D STEP Bottom:
  text ".Layer_Name" at 10193,-71 h60
M5 Assembly Top:
  lines w10: -292,-930.17 6308,-930.17 ; -292,-726.83 6310,-726.83 ; -292,-523.5 -292,-1133.5 3713,-1133.5 6310,-1133.5 6310,-523.5 -291.5,-523.5 -291.5,-1133.5 1284,-1133.5 ; 2173,-1133.5 2173,-523.5 ; 3440,-726.83 3440,-523.5 ; 4280,-726.83 4280,-523.5 ; 4902,-1140 4902,-937.17
  text "COMPONENTS MARKED 'DNP' SHOULD NOT BE POPULATED." at 1153.5,-318.5 h60
  text "ASSEMBLY VARIANT:" at 1153,-434 h60
  text ".VariantName" at 2189,-434 h60
  text "PCB VIEWED FROM TOP SIDE" at -228.5,-655.67 h60
  text "BOARD #:" at 2248,-655.67 h60
  text ".PRJ_Number" at 2793.5,-655.67 h60
  text "REV:" at 3638,-655.67 h60
  text ".PCB_Rev" at 3929.5,-655.67 h60
  text "SVN REV:" at 4476,-655.67 h60
  text ".VersionControl_RevNumber" at 4982,-655.67 h60
  text "TID #:" at 2248,-859 h60
  text ".TID" at 2793.5,-859 h60
  text "PLOT NAME =" at -228.5,-1064.34 h60
  text ".plot_File_Name" at 577,-1064.34 h60
  text "GENERATED    :" at 2250,-1064.34 h60
  text ".Print_Date" at 3119.5,-1064.34 h60
  text ".Print_Time" at 3848.5,-1064.34 h60
  text "TEXAS INSTRUMENTS" at 5113,-1064.34 h60
M6 Assembly Bottom:
  lines w10: -292.5,-727.33 6309.5,-727.33 ; -290.5,-930.67 6309.5,-930.67 ; 1115.5,-1140.5 1115.5,-937.67 ; 1737.5,-727.33 1737.5,-524 ; 2577.5,-727.33 2577.5,-524 ; 3844.5,-1134 3844.5,-524 ; 4733.5,-1134 6309,-1134 6309,-524 -292.5,-524 -292.5,-1134 2304.5,-1134 6309.5,-1134 6309.5,-524
  text "COMPONENTS MARKED 'DNP' SHOULD NOT BE POPULATED." at 6102,-318 h60
  text ".VariantName" at 5058,-434 h60
  text "ASSEMBLY VARIANT:" at 6097,-434 h60
  text ".VersionControl_RevNumber" at 1035.5,-656.17 h60
  text "SVN REV:" at 1541.5,-656.17 h60
  text ".PCB_Rev" at 2088,-656.17 h60
  text "REV:" at 2379.5,-656.17 h60
  text ".PRJ_Number" at 3224,-656.17 h60
  text "BOARD #:" at 3769.5,-656.17 h60
  text "PCB VIEWED FROM BOTTOM SIDE" at 6246,-656.17 h60
  text ".TID" at 3224,-859.5 h60
  text "TID #:" at 3769.5,-859.5 h60
  text "TEXAS INSTRUMENTS" at 904.5,-1064.84 h60
  text ".Print_Time" at 2169,-1064.84 h60
  text ".Print_Date" at 2898,-1064.84 h60
  text "GENERATED    :" at 3767.5,-1064.84 h60
  text ".plot_File_Name" at 5440.5,-1064.84 h60
  text "PLOT NAME =" at 6246,-1064.84 h60
M9 Title Sheet:
  drawing of 57 lines, arcs and shapes, not listed
  text "1" at 739.84,8036.5 h70
  text "2" at 3235.5,8036.5 h70
  text "3" at 5724.84,8036.5 h70
  text "4" at 8231.51,8036.5 h70
  text "5" at 10730.5,8036.5 h70
  text "6" at 13235.5,8036.5 h70
  text "A" at -416.5,6893.5 h70
  text "A" at 14383.5,6893.5 h70
  text "B" at -416.5,4513.5 h70
  text "B" at 14383.5,4513.5 h70
  text "C" at -416.5,2138.5 h70
  text "C" at 14383.5,2138.5 h70
  text "PROJECT TITLE:" at 11343.5,277.5 h45
  text ".PRJ_Title" at 11393.5,144.17 h70
  text "DESIGNED FOR:" at 11343.5,-23.5 h45
  text ".PRJ_Customer" at 11393.5,-163.5 h70
  text "D" at -416.5,-231.5 h70
  text "D" at 14383.5,-231.5 h70
  text "FILE NAME:" at 11343.5,-323.5 h45
  text ".PCB_File_Name_No_Path" at 11393.5,-443.5 h70
  text "Texas Instruments (TI) and/or its licensors do not warrant the accuracy or completeness of this specification" at 6374,-605.34 h45
  text "ENGINEER:" at 11343.5,-613.5 h45
  text "LAYOUT BY:" at 12848.5,-613.5 h45
  text "or any information contained therein. TI and/or its licensors do not warrant that this design will meet" at 6329.01,-718 h45
  text ".PRJ_Engineer" at 11393.5,-768.49 h70
  text ".PCB_Layout" at 12899,-768.49 h70
  text "the specifications, will be suitable for your application or fit for any particular purpose, or will operate in" at 6329.01,-830.67 h45
  text ".Layer_Name" at 577,-858.49 h60
  text "ALTIUM DESIGNER VERSION:" at 12848.5,-923.5 h45
  text "an implementation. TI and/or its licensors do not warrant that the design is production worthy. You should" at 6329.01,-943.33 h45
  text "completely validate and test your design implementation to confirm the system functionality for your application." at 6374,-1056 h45
  text ".print_Scale" at 11393.5,-1056.83 h70
  text ".Application_BuildNumber" at 12899,-1056.83 h70
  text "1" at 739.84,-1263.5 h70
  text "2" at 3235.5,-1263.5 h70
  text "3" at 5724.84,-1263.5 h70
  text "4" at 8231.51,-1263.5 h70
  text "5" at 10730.5,-1263.5 h70
  text "6" at 13235.5,-1263.5 h70
M10 Fab Notes:
  drawing of 201 lines, arcs and shapes, not listed
  text "DESIGN INFORMATION" at 12308.02,6618.17 h60
  text "0.25" at 12645,6497 h60
  text "MIN. TRACK WIDTH:" at 11663.46,6486.05 h60
  text "mm" at 12914.46,6486.05 h60
  text "0.25" at 12634,6373 h60
  text "MIN. CLEARANCE:" at 11663.46,6361.92 h60
  text "mm" at 12914.46,6361.92 h60
  text "19.685" at 12525,6249 h60
  text "MIN. VIA PAD SIZE:" at 11663.46,6237.8 h60
  text "MIL" at 12914.46,6237.8 h60
  text "0.05mm (2MIL)" at 12358.46,6107.9 h60
  text "MINIMUM ANNULAR RING" at 11334.23,6099.67 h60
  text "EXTERNAL" at 13066.46,6099.67 h60
  text "PER" at 11534.23,5989.55 h60
  text "IPC-D-275 CLASS 2 LEVEL C" at 11754.23,5989.54 h60
  text "MIL, HOLES" at 13242.46,5889.07 h60
  text "+/-" at 12850,5880.48 h60
  text "+/-" at 13704,5880.48 h60
  text "REGISTRATION TOLERANCES:" at 11334.23,5879.42 h60
  text "METAL" at 12534,5879.42 h60
  text "5" at 13110.2,5879.42 h60
  text "3" at 13943.2,5879.42 h60
  text "MIL" at 14059.46,5879.42 h60
  text "HOLE SIZE TOLERANCE (UNLESS OTHERWISE SPECIFIED):" at 11334.23,5781.1 h60
  text "+/-" at 13704,5778.23 h60
  text "3" at 13943.2,5777.17 h60
  text "MIL" at 14059.46,5777.17 h60
  text "MATERIAL:" at 11259.46,5639.52 h60
  text "FR-4 High Tg" at 12245.9,5511 h60
  text "X" at 12101.46,5503.01 h60
  text "FR-408" at 11680.46,5498.49 h60
  text "OTHER" at 13168.46,5498.49 h60
  text "62 MIL (1.6mm) +/-10%" at 12000.56,5355.46 h60
  text "X" at 11880.46,5353.01 h60
  text "THICKNESS:" at 11334.23,5347.24 h60
  text "OTHER" at 13285.46,5347.24 h60
  text "TOLERANCE:" at 11334.23,5208.92 h60
  text "X" at 12182.46,5208.92 h60
  text "ANSI IPC-6012 TYPE 3 CLASS 2" at 12360.48,5208.92 h60
  text "OTHER +/-" at 12360.46,5064.73 h60
  text "BOW & TWIST:" at 11334.23,4919.54 h60
  text "X" at 12182.46,4919.54 h60
  text "ANSI IPC-6012 TYPE 3 CLASS 2" at 12360.48,4919.54 h60
  text "OTHER +/-" at 12360.46,4772.85 h60
  text "DRILLING:" at 11259.46,4642.23 h60
  text "NC_DRILL FILES" at 13020.46,4537.04 h60
  text "REFERENCE:" at 11334.23,4533.1 h60
  text "X" at 11991.46,4533.01 h60
  text "AS SHOWN" at 12169.46,4533.1 h60
  text "X" at 12892.46,4533.1 h60
  text "OTHER" at 13318.46,4390.85 h60
  text "PTH COPPER THICKNESS:" at 11333.91,4387.32 h60
  text "X" at 12473.14,4387.32 h60
  text "20-30 um" at 12601.14,4387.32 h60
  text "BOARD FINISH:" at 11259.46,4239.73 h60
  text "SILKSCREEN:" at 11414.68,4129.6 h60
  text "X" at 12372.46,4129.6 h60
  text "TOP" at 12489.46,4129.6 h60
  text "X" at 12882.46,4129.6 h60
  text "BOTTOM" at 13000.46,4129.6 h60
  text "SILKSCREEN COLOR:" at 11414.68,3974.41 h60
  text "X" at 12371.46,3974.41 h60
  text "WHITE" at 12489.46,3974.41 h60
  text "OTHER" at 13000.46,3974.41 h60
  text "X" at 12502.46,3830.96 h60
  text "GREEN" at 12620.46,3830.96 h60
  text "OTHER" at 13238.46,3830.96 h60
  text "SOLDER RESIST COLOR:" at 11414.68,3824.1 h60
  text "X" at 12502.46,3676.71 h60
  text "MATTE" at 12620.46,3676.71 h60
  text "SEMI-GLOSS" at 13238,3676.07 h60
  text "IMMERSION GOLD (ENIG)" at 12320.46,3503.94 h60
  text "ENEPIG" at 13658,3496.72 h60
  text "SURFACE FINISH:" at 11259.46,3495.72 h60
  text "X" at 12142.46,3495.72 h60
  text "IMM. TIN/SILVER OR EQUIV" at 11589,3358.4 h60
  text "OTHER" at 13020.46,3354.47 h60
  text "ARRAY/PANEL:" at 11259.46,3199.09 h60
  text "CUT AND TRIM PER M1 BOARD OUTLINE" at 12320.46,3190.87 h60
  text "N.C. ROUTE" at 12320.46,3054.9 h60
  text "X" at 13008.46,3054.9 h60
  text "V. SCORE" at 13186.46,3054.9 h60
  text "CERTIFICATION:" at 11259.46,2925.77 h60
  text "MATERIALS AND WORKMANSHIP FOR ALL PCBS" at 11984.46,2925.77 h60
  text "TO MEET OR EXCEED THE REQUIREMENTS OF:" at 11984.46,2831.71 h60
  text "X" at 11621.97,2703.08 h60
  text "ANSI IPC-A-600F CLASS ->" at 11749.96,2703.08 h60
  text "X" at 13397.97,2703.08 h60
  text "2" at 13507.96,2703.08 h60
  text "1" at 13192.96,2701.58 h60
  text "3" at 13861.96,2701.58 h60
  text "X" at 12433.97,2555.39 h60
  text "RoHS" at 12561.96,2555.39 h60
  text "OTHER" at 13206.36,2555.39 h60
  text "PER ORDER" at 13603.42,2555.39 h60
  text "ALL BOARDS MUST MEET OR EXCEED UL94-V0 REQUIREMENTS." at 11287,2401.57 h60
  text "PCB MUST BEAR THE UL94V-0 UL REGISTERED MATERIAL ID NUMBER" at 11287,2285.5 h60
  text "ADDITIONAL REQUIREMENTS:" at 11259.46,2116.08 h60
  text "MICROSECTION:" at 11334.23,2008.95 h60
  text "YES" at 12239.96,2008.95 h60
  text "REQUIRED" at 13101.46,1864.62 h60
  text "BARE BOARD ELEC. TEST:" at 11334.23,1861.76 h60
  text "NONE" at 12639.96,1861.76 h60
  text "X" at 12983.46,1861.76 h60
  text "PER ORDER" at 13693.46,1861.76 h60
  text "9.8 MIL & 7.87 MIL VIAS REQUIRE NON-CONDUCTIVE FILL AND PLANARIZE" at 11520,1647 h50
  text "XX MIL VIAS REQUIRE CONDUCTIVE FILL AND PLANARIZE" at 11510.38,1552.84 h60
  text "OUTER XX MIL TRACES REQUIRE 50 OHM SINGLE-ENDED IMPEDANCE" at 11509.39,1389.46 h58
  text "LAYER 2 & 3 (INNER LAYERS) XX MIL WIDE, XX MIL SPACE / TRACES REQUIRE 100 OHM DIFFERENTIAL IMPEDANCE" at 11501.39,1153.74 h60
  text "X" at 11390.02,1036.45 h60
  text "REMOVE PORTION OF SILKSCREEN THAT ARE OVERLAPPING COMPONENT COPPER PADS (SUCH AS L1 SILKSCREEN ON L2)" at 11520,1036.45 h48
  text ".Layer_Name" at 577,-858.49 h60
M11 Gerber Information:
  lines w10: -292,-930.17 6308,-930.17 ; -292,-726.83 6310,-726.83 ; -292,-523.5 -292,-1133.5 3713,-1133.5 6310,-1133.5 6310,-523.5 -291.5,-523.5 -291.5,-1133.5 1284,-1133.5 ; 2173,-1133.5 2173,-523.5 ; 3440,-726.83 3440,-523.5 ; 4280,-726.83 4280,-523.5 ; 4902,-1140 4902,-937.17
  text "ALL ARTWORK VIEWED FROM TOP SIDE" at -228.5,-655.67 h60
  text "BOARD #:" at 2248,-655.67 h60
  text ".PRJ_Number" at 2793.5,-655.67 h60
  text "REV:" at 3638,-655.67 h60
  text ".PCB_Rev" at 3929.5,-655.67 h60
  text "SVN REV:" at 4476,-655.67 h60
  text ".VersionControl_RevNumber" at 4982,-655.67 h60
  text "LAYER NAME =" at -228.5,-858.49 h60
  text "TID #:" at 2248,-859 h60
  text ".TID" at 2793.5,-859 h60
  text "PLOT NAME =" at -228.5,-1064.34 h60
  text ".plot_File_Name" at 577,-1064.34 h60
  text "GENERATED    :" at 2250,-1064.34 h60
  text ".Print_Date" at 3119.5,-1064.34 h60
  text ".Print_Time" at 3848.5,-1064.34 h60
  text "TEXAS INSTRUMENTS" at 5113,-1064.34 h60
M12 Stackup:
  drawing of 536 lines, arcs and shapes, not listed
  text "Layer" at 6243.5,5702.01 h60
  text "Name" at 6653.41,5702.01 h60
  text "Material" at 7613.15,5702.01 h60
  text "Thickness" at 8472.92,5702.01 h60
  text "Constant" at 9122.75,5702.01 h60
  text "Board Layer Stack" at 9692.61,5702.01 h60
  text "Top Overlay" at 6653.41,5582.01 h60
  text "Top Solder" at 6653.41,5462.01 h60
  text "Solder Resist" at 7613.15,5462.01 h60
  text "0.60mil" at 8472.92,5462.01 h60
  text "3.5" at 9122.75,5462.01 h60
  text "1" at 6243.5,5342.01 h60
  text "Top Layer" at 6653.41,5342.01 h60
  text "2.80mil" at 8472.92,5342.01 h60
  text "Dielectric 1" at 6653.41,5222.01 h60
  text "FR-4 High-Tg" at 7613.15,5222.01 h60
  text "9.00mil" at 8472.92,5222.01 h60
  text "4.2" at 9122.75,5222.01 h60
  text "2" at 6243.5,5102.01 h60
  text "Layer 2 - PGND" at 6653.41,5102.01 h60
  text "2.80mil" at 8472.92,5102.01 h60
  text "Dielectric 2" at 6653.41,4982.01 h60
  text "FR-4 High-Tg" at 7613.15,4982.01 h60
  text "10.00mil" at 8472.92,4982.01 h60
  text "4.2" at 9122.75,4982.01 h60
  text "3" at 6243.5,4862.01 h60
  text "Layer 3" at 6653.41,4862.01 h60
  text "2.80mil" at 8472.92,4862.01 h60
  text "Dielectric 4" at 6653.41,4742.01 h60
  text "FR-4 High-Tg" at 7613.15,4742.01 h60
  text "6.00mil" at 8472.92,4742.01 h60
  text "4.2" at 9122.75,4742.01 h60
  text "4" at 6243.5,4622.01 h60
  text "Layer 4" at 6653.41,4622.01 h60
  text "2.80mil" at 8472.92,4622.01 h60
  text "Dielectric 5" at 6653.41,4502.01 h60
  text "FR-4 High-Tg" at 7613.15,4502.01 h60
  text "10.00mil" at 8472.92,4502.01 h60
  text "4.2" at 9122.75,4502.01 h60
  text "5" at 6243.5,4382.01 h60
  text "Layer 5 - PGND" at 6653.41,4382.01 h60
  text "2.80mil" at 8472.92,4382.01 h60
  text "Dielectric 3" at 6653.41,4262.01 h60
  text "FR-4 High-Tg" at 7613.15,4262.01 h60
  text "9.00mil" at 8472.92,4262.01 h60
  text "4.2" at 9122.75,4262.01 h60
  text "6" at 6243.5,4142.01 h60
  text "Bottom Layer" at 6653.41,4142.01 h60
  text "2.80mil" at 8472.92,4142.01 h60
  text "Bottom Solder" at 6653.41,4022.01 h60
  text "Solder Resist" at 7613.15,4022.01 h60
  text "0.60mil" at 8472.92,4022.01 h60
  text "3.5" at 9122.75,4022.01 h60
  text "Bottom Overlay" at 6653.41,3902.01 h60
  text ".Layer_Name" at 577,-858.49 h60
M13 Component Bodies Top:
  text ".Layer_Name" at 577,-858.49 h60
M14 Component Bodies Bottom:
  text ".Layer_Name" at 577,-858.49 h60
M15 Courtyards Top:
  text ".Layer_Name" at 577,-858.49 h60
M16 Courtyards Bottom:
  text ".Layer_Name" at 577,-858.49 h60
Drill Drawing:
  circle w10: c149.62,7064.83 r33.33
  circle w10: c149.62,6464.83 r20
  circle w10: c149.62,6464.83 r33.33
  lines w10: 116.29,6281.5 149.62,6298.17 182.96,6281.5 166.29,6314.83 182.96,6348.17 149.62,6331.5 116.29,6348.17 132.96,6314.83 116.29,6281.5 ; 116.29,6598.17 132.96,6598.17 149.62,6581.5 166.29,6598.17 182.96,6598.17 166.29,6614.83 182.96,6631.5 166.29,6631.5 149.62,6648.17 132.96,6631.5 116.29,6631.5 132.96,6614.83 116.29,6598.17 ; 116.29,6798.17 182.96,6798.17 149.62,6731.5 116.29,6798.17 ; 116.29,6881.5 182.96,6881.5 182.96,6948.17 116.29,6948.17 116.29,6881.5 ; 116.29,7198.17 132.96,7198.17 132.96,7181.5 166.29,7181.5 166.29,7198.17 182.96,7198.17 182.96,7231.5 166.29,7231.5 166.29,7248.17 132.96,7248.17 132.96,7231.5 116.29,7231.5 116.29,7198.17 ; 116.29,7331.5 116.29,7348.17 132.96,7364.83 116.29,7381.5 116.29,7398.17 132.96,7398.17 149.62,7381.5 166.29,7398.17 182.96,7398.17 182.96,7381.5 166.29,7364.83 182.96,7348.17 182.96,7331.5 166.29,7331.5 149.62,7348.17 132.96,7331.5 116.29,7331.5 ; 116.29,7514.83 149.62,7481.5 182.96,7514.83 149.62,7548.17 116.29,7514.83 ; 116.29,7631.5 182.96,7631.5 182.96,7698.17 116.29,7698.17 116.29,7631.5 ; 129.62,6894.83 169.62,6894.83 169.62,6934.83 129.62,6934.83 129.62,6894.83
  lines w15: 56.5,6236.5 10897.48,6236.5 ; 56.5,7736.5 10897.48,7736.5 ; 607.38,6086.5 607.38,7886.5 ; 1257.2,6086.5 1257.2,7886.5 ; 2386.87,6086.5 2386.87,7886.5 ; 2892.75,6086.5 2892.75,7886.5 ; 3626.55,6086.5 3626.55,7886.5 ; 5126.1,6086.5 5126.1,7886.5 ; 5715.95,6086.5 5715.95,7886.5 ; 6461.75,6086.5 6461.75,7886.5 ; 7331.5,6086.5 7331.5,7886.5 ; 8185.26,6086.5 8185.26,7886.5 ; 9518.87,6086.5 9518.87,7886.5 ; 56.5,6086.5 10897.48,6086.5 10897.48,7886.5 56.5,7886.5 56.5,6086.5
  text "Symbol" at 146.5,7781.5 h72
  text "Count" at 652.38,7781.5 h72
  text "Hole Size" at 1302.2,7781.5 h72
  text "Plated" at 2431.87,7781.5 h72
  text "Hole Type" at 2937.75,7781.5 h72
  text "Drill Layer Pair" at 3671.55,7781.5 h72
  text "Via/Pad" at 5171.1,7781.5 h72
  text "Pad Shape" at 5760.95,7781.5 h72
  text "Template" at 6506.75,7781.5 h72
  text "Description" at 7376.5,7781.5 h72
  text "Hole Tolerance (+)" at 8230.26,7781.5 h72
  text "Hole Tolerance (-)" at 9563.87,7781.5 h72
  text "2" at 652.38,7631.5 h60
  text "43.31mil (1.100mm)" at 1302.2,7631.5 h60
  text "PTH" at 2431.87,7631.5 h60
  text "Round" at 2937.75,7631.5 h60
  text "Top Layer - Bottom Layer" at 3671.55,7631.5 h60
  text "Pad" at 5171.1,7631.5 h60
  text "(Mixed)" at 5760.95,7631.5 h60
  text "(Mixed)" at 6506.75,7631.5 h60
  text "2" at 652.38,7481.5 h60
  text "114.17mil (2.900mm)" at 1302.2,7481.5 h60
  text "PTH" at 2431.87,7481.5 h60
  text "Round" at 2937.75,7481.5 h60
  text "Top Layer - Bottom Layer" at 3671.55,7481.5 h60
  text "Pad" at 5171.1,7481.5 h60
  text "Rounded" at 5760.95,7481.5 h60
  text "c508h290m0mx0" at 6506.75,7481.5 h60
  text "4" at 652.38,7331.5 h60
  text "40.16mil (1.020mm)" at 1302.2,7331.5 h60
  text "PTH" at 2431.87,7331.5 h60
  text "Round" at 2937.75,7331.5 h60
  text "Top Layer - Bottom Layer" at 3671.55,7331.5 h60
  text "Pad" at 5171.1,7331.5 h60
  text "(Mixed)" at 5760.95,7331.5 h60
  text "(Mixed)" at 6506.75,7331.5 h60
  text "6" at 652.38,7181.5 h60
  text "62.99mil (1.600mm)" at 1302.2,7181.5 h60
  text "PTH" at 2431.87,7181.5 h60
  text "Round" at 2937.75,7181.5 h60
  text "Top Layer - Bottom Layer" at 3671.55,7181.5 h60
  text "Pad" at 5171.1,7181.5 h60
  text "(Mixed)" at 5760.95,7181.5 h60
  text "(Mixed)" at 6506.75,7181.5 h60
  text "16" at 652.38,7031.5 h60
  text "7.87mil (0.200mm)" at 1302.2,7031.5 h60
  text "PTH" at 2431.87,7031.5 h60
  text "Round" at 2937.75,7031.5 h60
  text "Top Layer - Bottom Layer" at 3671.55,7031.5 h60
  text "Via" at 5171.1,7031.5 h60
  text "Rounded" at 5760.95,7031.5 h60
  text "v50h20m0mx0" at 6506.75,7031.5 h60
  text "21" at 652.38,6881.5 h60
  text "20.00mil (0.508mm)" at 1302.2,6881.5 h60
  text "PTH" at 2431.87,6881.5 h60
  text "Round" at 2937.75,6881.5 h60
  text "Top Layer - Bottom Layer" at 3671.55,6881.5 h60
  text "Via" at 5171.1,6881.5 h60
  text "Rounded" at 5760.95,6881.5 h60
  text "v102h51" at 6506.75,6881.5 h60
  text "91" at 652.38,6731.5 h60
  text "40.00mil (1.016mm)" at 1302.2,6731.5 h60
  text "PTH" at 2431.87,6731.5 h60
  text "Round" at 2937.75,6731.5 h60
  text "Top Layer - Bottom Layer" at 3671.55,6731.5 h60
  text "Pad" at 5171.1,6731.5 h60
  text "(Mixed)" at 5760.95,6731.5 h60
  text "(Mixed)" at 6506.75,6731.5 h60
  text "105" at 652.38,6581.5 h60
  text "14.00mil (0.356mm)" at 1302.2,6581.5 h60
  text "PTH" at 2431.87,6581.5 h60
  text "Round" at 2937.75,6581.5 h60
  text "Top Layer - Bottom Layer" at 3671.55,6581.5 h60
  text "Via" at 5171.1,6581.5 h60
  text "Rounded" at 5760.95,6581.5 h60
  text "v61h36" at 6506.75,6581.5 h60
  text "132" at 652.38,6431.5 h60
  text "9.80mil (0.249mm)" at 1302.2,6431.5 h60
  text "PTH" at 2431.87,6431.5 h60
  text "Round" at 2937.75,6431.5 h60
  text "Top Layer - Bottom Layer" at 3671.55,6431.5 h60
  text "Via" at 5171.1,6431.5 h60
  text "Rounded" at 5760.95,6431.5 h60
  text "v61h25(1)" at 6506.75,6431.5 h60
  text "653" at 652.38,6281.5 h60
  text "10.00mil (0.254mm)" at 1302.2,6281.5 h60
  text "PTH" at 2431.87,6281.5 h60
  text "Round" at 2937.75,6281.5 h60
  text "Top Layer - Bottom Layer" at 3671.55,6281.5 h60
  text "Via" at 5171.1,6281.5 h60
  text "Rounded" at 5760.95,6281.5 h60
  text "(Mixed)" at 6506.75,6281.5 h60
  text "1032 Total" at 652.38,6131.5 h60
Mechanical 17:
  text ".Layer_Name" at 577,-858.49 h60
Mechanical 18:
  text ".Layer_Name" at 577,-858.49 h60
Mechanical 19:
  text ".Layer_Name" at 577,-858.49 h60

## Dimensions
0,-400 to 1000,-400 on M2 Board Dimensions
0,0 to 4409,3307 on M2 Board Dimensions
0,0 to 4409.45,0 on M2 Board Dimensions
